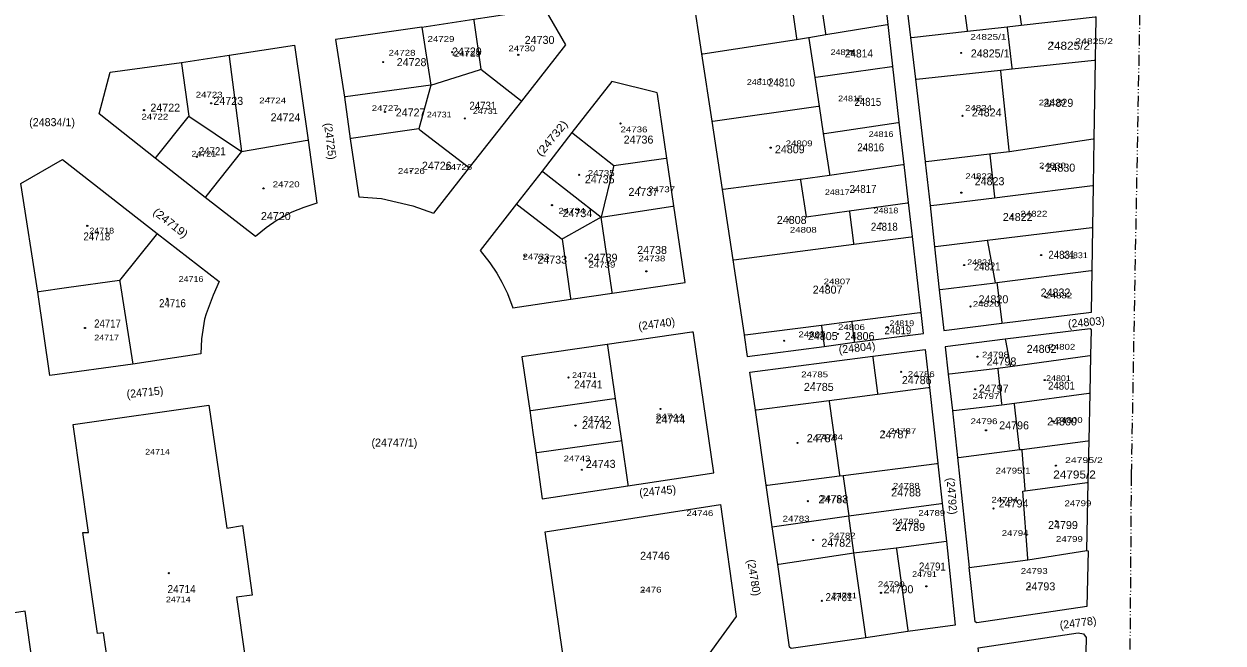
# Model space of a CAD drawing. Extents: x 649608 to 651081, y 237980 to 241202.
# Drawn here: x 650066 to 650605, y 239944 to 240222 of the extents above; entities that cross this region are included whole.
import ezdxf

# ---------------------------------------------------------------- set-up
doc = ezdxf.new("R2010")
doc.units = 0
doc.header["$PDMODE"] = 32
doc.header["$PDSIZE"] = 0.5
doc.linetypes.add('DASH_DOUBLE_DOT', pattern=[9.2, 5, -1.2, 0.3, -1.2, 0.3, -1.2])
for name, color, linetype in [('19', 7, 'Continuous'), ('20', 7, 'Continuous'), ('6', 7, 'Continuous')]:
    doc.layers.add(name, color=color, linetype=linetype)
for name, color, linetype, lineweight in [('3', 7, 'Continuous', 13), ('5', 7, 'Continuous', 13), ('52', 7, 'DASH_DOUBLE_DOT', 13)]:
    doc.layers.add(name, color=color, linetype=linetype, lineweight=lineweight)

msp = doc.modelspace()

# ---------------------------------------------------------------- linework, layer by layer
at = {"layer": '3'}
msp.add_line((650077.677, 240064.155), (650072.262, 240101.751), dxfattribs=at)
for points in [[(650460.37, 240253.655), (650464.813, 240216.218), (650467.034, 240197.497), (650471.435, 240160.411)], [(650459.759, 240178.093), (650456.889, 240203.161), (650456.873, 240203.307), (650454.806, 240222.136), (650451.519, 240252.086)], [(650409.196, 240245.982), (650369.92, 240239.938), (650366.735, 240235.721), (650370.821, 240208.803), (650375.407, 240178.587), (650380.061, 240147.931), (650384.882, 240116.168), (650389.996, 240082.478)], [(650245.029, 240220.902), (650268.31, 240224.434), (650300.106, 240229.259)], [(650300.106, 240229.259), (650309.685, 240212.852), (650289.846, 240187.623), (650266.349, 240157.741), (650250.168, 240137.164)], [(650547.448, 240170.665), (650547.985, 240206.022), (650547.986, 240206.073), (650548.41, 240225.505)], [(650245.029, 240220.902), (650206.077, 240215.362), (650210.154, 240189.431), (650212.761, 240170.721)], [(650158.302, 240208.221), (650187.759, 240212.714), (650193.84, 240170.093)], [(650125.028, 240162.003), (650099.773, 240181.845), (650104.736, 240200.583), (650136.809, 240205.043), (650158.302, 240208.221)], [(650350.909, 240191.305), (650350.427, 240191.426), (650330.438, 240196.449), (650312.536, 240173.446), (650299.057, 240156.125), (650287.566, 240141.36)], [(650355.222, 240162.022), (650351.001, 240190.68), (650350.909, 240191.305)], [(650439.582, 240079.132), (650439.664, 240079.144), (650470.631, 240083.119), (650469.553, 240092.532), (650465.643, 240126.687), (650463.896, 240141.953), (650461.932, 240159.11), (650459.759, 240178.093)], [(650193.84, 240170.093), (650197.735, 240141.656), (650191.852, 240139.818), (650186.467, 240137.627), (650179.884, 240134.109), (650174.936, 240130.596), (650170.183, 240126.658)], [(650212.761, 240170.721), (650216.609, 240144.52), (650226.785, 240143.745), (650240.88, 240140.585), (650250.168, 240137.164)], [(650505.972, 240087.695), (650546.262, 240092.74), (650546.547, 240111.483), (650546.842, 240130.84), (650547.128, 240149.718), (650547.448, 240170.665)], [(650072.262, 240101.751), (650064.598, 240150.503), (650083.395, 240161.316), (650125.86, 240128.041)], [(650170.183, 240126.658), (650147.491, 240144.257), (650125.028, 240162.003)], [(650330.631, 240101.23), (650363.469, 240106.028), (650358.392, 240140.495), (650355.222, 240162.022)], [(650471.435, 240160.411), (650471.464, 240160.171), (650473.598, 240140.628), (650475.618, 240122.131), (650477.734, 240102.751)], [(650287.566, 240141.36), (650271.262, 240120.41), (650275.629, 240114.908), (650278.668, 240110.188), (650280.993, 240106.15), (650283.522, 240101.127), (650285.874, 240094.69), (650311.995, 240098.507), (650330.631, 240101.23)], [(650125.86, 240128.041), (650153.76, 240106.551), (650151.042, 240100.376), (650147.993, 240091.921), (650147.259, 240089.472), (650145.941, 240080.672), (650145.556, 240074.02), (650114.914, 240069.344), (650077.677, 240064.155)], [(650477.734, 240102.751), (650479.737, 240084.41), (650505.972, 240087.695)], [(650545.951, 240073.247), (650546.192, 240084.737), (650545.656, 240085.242), (650507.391, 240080.473)], [(650367.096, 240083.725), (650366.506, 240083.64), (650328.379, 240078.162)], [(650337.721, 240014.61), (650376.316, 240020.498), (650367.171, 240083.212), (650367.096, 240083.725)], [(650389.996, 240082.478), (650390.018, 240082.332), (650391.378, 240072.814), (650426.009, 240077.194)], [(650507.391, 240080.473), (650480.432, 240077.114), (650481.82, 240064.866), (650483.681, 240048.453)], [(650328.379, 240078.162), (650290.024, 240072.651), (650293.54, 240048.426)], [(650426.009, 240077.194), (650426.018, 240077.195), (650439.582, 240079.132)], [(650447.844, 240072.874), (650471.376, 240075.899), (650473.291, 240058.802), (650477.109, 240024.718)], [(650395.057, 240048.659), (650392.582, 240065.771), (650447.844, 240072.874)], [(650544.103, 239985.437), (650544.75, 240016.162), (650545.145, 240034.936), (650545.592, 240056.262), (650545.951, 240073.247)], [(650088.141, 240042.191), (650149.19, 240050.902), (650157.293, 239995.611), (650164.347, 239996.723), (650168.634, 239965.476), (650161.633, 239964.565), (650169.588, 239908.656)], [(650293.54, 240048.426), (650294.974, 240038.545), (650296.256, 240029.457)], [(650402.654, 239996.132), (650399.95, 240014.828), (650395.057, 240048.659)], [(650483.681, 240048.453), (650483.694, 240048.334), (650485.946, 240027.287), (650491.239, 239977.817)], [(650169.588, 239908.656), (650108.765, 239899.717), (650101.708, 239948.509), (650099.051, 239948.199), (650092.508, 239993.558), (650094.984, 239993.566), (650088.141, 240042.191)], [(650296.256, 240029.457), (650299.181, 240008.73), (650337.721, 240014.61)], [(650477.109, 240024.718), (650477.131, 240024.524), (650479.074, 240006.776), (650480.943, 239989.699)], [(650444.775, 239946.285), (650411.125, 239941.373), (650410.377, 239941.975), (650405.07, 239979.206), (650402.654, 239996.132)], [(650480.943, 239989.699), (650484.938, 239951.984), (650463.613, 239949.096), (650444.775, 239946.285)], [(650544.103, 239985.437), (650544.781, 239985.332), (650544.163, 239960.292), (650494.592, 239952.965), (650493.943, 239953.442), (650491.239, 239977.817)], [(650071.051, 239926.074), (650066.514, 239958.205), (650038.223, 239953.835), (650015.835, 239950.432), (649993.523, 239946.827), (649971.163, 239943.727)]]:
    msp.add_lwpolyline(points, dxfattribs=at)
for points in [[(650379.366, 240006.183), (650386.357, 239955.842), (650374.029, 239938.824), (650309.84, 239928.724), (650300.505, 239993.965)], [(650541.896, 239857.35), (650505.729, 239851.839), (650495.324, 239941.714), (650540.294, 239948.511), (650542.677, 239948.068), (650543.767, 239946.296)]]:
    msp.add_lwpolyline(points, close=True, dxfattribs=at)
at = {"layer": '5'}
for p, q in [((650245.029, 240220.902), (650249.078, 240194.772)), ((650249.078, 240194.772), (650243.626, 240175.122)), ((650515.319, 240012.253), (650516.434, 240012.401)), ((650402.654, 239996.132), (650437.147, 240001.148))]:
    msp.add_line(p, q, dxfattribs=at)
for points in [[(650508.951, 240260.965), (650509.023, 240260.465), (650514.54, 240222.272), (650514.612, 240221.772)], [(650485.214, 240257.393), (650485.282, 240256.893), (650490.357, 240219.574), (650490.425, 240219.074)], [(650422.153, 240247.787), (650422.228, 240247.287), (650426.646, 240218.032), (650426.721, 240217.532)], [(650409.196, 240245.982), (650409.268, 240245.482), (650413.524, 240215.891), (650413.596, 240215.391)], [(650514.612, 240221.772), (650547.91, 240225.45), (650548.41, 240225.505)], [(650268.31, 240224.434), (650268.38, 240223.934), (650271.472, 240201.911)], [(650426.721, 240217.532), (650454.306, 240222.054), (650454.806, 240222.136)], [(650464.813, 240216.218), (650465.313, 240216.274), (650490.425, 240219.074), (650508.256, 240221.063)], [(650508.256, 240221.063), (650514.585, 240221.769), (650514.612, 240221.772)], [(650508.256, 240221.063), (650508.316, 240220.563), (650510.473, 240202.605), (650510.533, 240202.105)], [(650370.821, 240208.803), (650371.321, 240208.88), (650413.525, 240215.38), (650413.596, 240215.391)], [(650413.596, 240215.391), (650418.994, 240216.265), (650419.023, 240216.27), (650426.721, 240217.532)], [(650419.023, 240216.27), (650419.099, 240215.77), (650421.759, 240198.257), (650423.715, 240185.381), (650425.591, 240173.032)], [(650136.809, 240205.043), (650136.878, 240204.543), (650140.128, 240180.885), (650163.898, 240165.01)], [(650158.302, 240208.221), (650158.367, 240207.721), (650163.898, 240165.01)], [(650510.533, 240202.105), (650547.486, 240206.02), (650547.986, 240206.073)], [(650249.078, 240194.772), (650270.972, 240201.752), (650271.472, 240201.911)], [(650271.472, 240201.911), (650289.346, 240188.012), (650289.846, 240187.623)], [(650421.759, 240198.257), (650422.259, 240198.329), (650456.373, 240203.235), (650456.873, 240203.307)], [(650467.034, 240197.497), (650467.534, 240197.55), (650505.242, 240201.545), (650510.533, 240202.105)], [(650505.242, 240201.545), (650505.296, 240201.045), (650509.108, 240165.48), (650509.162, 240164.98)], [(650249.078, 240194.772), (650210.654, 240189.5), (650210.154, 240189.431)], [(650375.407, 240178.587), (650375.907, 240178.657), (650423.215, 240185.311), (650423.715, 240185.381)], [(650140.128, 240180.885), (650139.728, 240180.385), (650125.428, 240162.503), (650125.028, 240162.003)], [(650425.591, 240173.032), (650426.091, 240173.106), (650459.259, 240178.019), (650459.759, 240178.093)], [(650243.626, 240175.122), (650213.261, 240170.792), (650212.761, 240170.721)], [(650243.626, 240175.122), (650244.126, 240174.74), (650265.849, 240158.123), (650266.349, 240157.741)], [(650312.536, 240173.446), (650313.037, 240173.052), (650331.361, 240158.63)], [(650425.591, 240173.032), (650428.351, 240154.86), (650428.427, 240154.36)], [(650163.898, 240165.01), (650193.34, 240170.008), (650193.84, 240170.093)], [(650509.162, 240164.98), (650509.317, 240164.999), (650546.947, 240170.591), (650547.448, 240170.665)], [(650163.898, 240165.01), (650147.886, 240144.757), (650147.491, 240144.257)], [(650331.361, 240158.63), (650354.722, 240161.951), (650355.222, 240162.022)], [(650471.435, 240160.411), (650471.936, 240160.472), (650500.379, 240163.916), (650509.162, 240164.98)], [(650500.379, 240163.916), (650500.436, 240163.416), (650502.571, 240144.62), (650502.628, 240144.12)], [(650299.057, 240156.125), (650299.557, 240155.736), (650325.588, 240135.477)], [(650331.361, 240158.63), (650331.236, 240158.13), (650325.588, 240135.477)], [(650428.427, 240154.36), (650461.432, 240159.039), (650461.932, 240159.11)], [(650380.061, 240147.931), (650380.561, 240147.996), (650415.222, 240152.488), (650415.26, 240152.493), (650428.427, 240154.36)], [(650415.26, 240152.493), (650415.337, 240151.993), (650417.881, 240135.578), (650437.28, 240138.266)], [(650502.628, 240144.12), (650508.4, 240144.814), (650546.629, 240149.655), (650547.128, 240149.718)], [(650287.566, 240141.36), (650288.066, 240140.972), (650308.044, 240125.473)], [(650325.588, 240135.477), (650357.892, 240140.419), (650358.392, 240140.495)], [(650437.28, 240138.266), (650463.396, 240141.884), (650463.896, 240141.953)], [(650473.598, 240140.628), (650474.098, 240140.688), (650502.628, 240144.12)], [(650325.588, 240135.477), (650308.544, 240125.758), (650308.044, 240125.473)], [(650330.631, 240101.23), (650330.557, 240101.73), (650325.588, 240135.477)], [(650437.28, 240138.266), (650437.346, 240137.766), (650439.187, 240123.75), (650439.253, 240123.25)], [(650499.333, 240125.031), (650546.341, 240130.779), (650546.842, 240130.84)], [(650125.86, 240128.041), (650125.46, 240127.541), (650109.022, 240106.971)], [(650308.044, 240125.473), (650311.922, 240099.007), (650311.995, 240098.507)], [(650384.882, 240116.168), (650385.382, 240116.233), (650439.253, 240123.25)], [(650439.253, 240123.25), (650465.143, 240126.622), (650465.643, 240126.687)], [(650475.618, 240122.131), (650476.118, 240122.192), (650499.333, 240125.031)], [(650499.333, 240125.031), (650499.426, 240124.531), (650502.886, 240105.943)], [(650109.022, 240106.971), (650085.163, 240103.599), (650072.762, 240101.823), (650072.262, 240101.751)], [(650109.022, 240106.971), (650109.1, 240106.471), (650114.914, 240069.344)], [(650503.673, 240106.043), (650546.047, 240111.42), (650546.547, 240111.483)], [(650477.734, 240102.751), (650478.234, 240102.814), (650502.886, 240105.943), (650503.673, 240106.043)], [(650503.673, 240106.043), (650505.909, 240088.195), (650505.972, 240087.695)], [(650438.352, 240088.589), (650469.053, 240092.469), (650469.553, 240092.532)], [(650389.996, 240082.478), (650390.496, 240082.541), (650424.708, 240086.865), (650438.352, 240088.589)], [(650424.708, 240086.865), (650424.775, 240086.365), (650425.942, 240077.694), (650426.009, 240077.194)], [(650438.352, 240088.589), (650438.417, 240088.089), (650439.517, 240079.632), (650439.582, 240079.132)], [(650507.391, 240080.473), (650507.487, 240079.973), (650509.626, 240068.796), (650509.722, 240068.296)], [(650328.379, 240078.162), (650328.452, 240077.662), (650331.951, 240053.863), (650334.735, 240034.921)], [(650447.844, 240072.874), (650447.908, 240072.374), (650449.973, 240056.287), (650450.037, 240055.787)], [(650509.722, 240068.296), (650545.45, 240073.179), (650545.951, 240073.247)], [(650481.82, 240064.866), (650482.32, 240064.925), (650504.076, 240067.513), (650509.722, 240068.296)], [(650504.076, 240067.513), (650504.131, 240067.013), (650505.817, 240051.54), (650505.872, 240051.04)], [(650450.037, 240055.787), (650472.791, 240058.737), (650473.291, 240058.802)], [(650293.54, 240048.426), (650294.04, 240048.497), (650331.451, 240053.792), (650331.951, 240053.863)], [(650395.057, 240048.659), (650395.557, 240048.724), (650428.194, 240052.955), (650450.037, 240055.787)], [(650428.194, 240052.955), (650428.263, 240052.455), (650432.806, 240019.548), (650432.875, 240019.048)], [(650511.602, 240051.793), (650545.093, 240056.196), (650545.592, 240056.262)], [(650483.681, 240048.453), (650484.18, 240048.511), (650505.872, 240051.04), (650511.602, 240051.793)], [(650513.938, 240030.85), (650513.882, 240031.35), (650511.658, 240051.293), (650511.602, 240051.793)], [(650296.256, 240029.457), (650296.756, 240029.528), (650334.235, 240034.85), (650334.735, 240034.921)], [(650334.735, 240034.921), (650337.648, 240015.11), (650337.721, 240014.61)], [(650514.967, 240030.918), (650544.644, 240034.869), (650545.145, 240034.936)], [(650485.946, 240027.287), (650486.446, 240027.351), (650513.938, 240030.85)], [(650513.938, 240030.85), (650514.959, 240030.917), (650514.967, 240030.918)], [(650516.434, 240012.401), (650516.394, 240012.901), (650515.007, 240030.418), (650514.967, 240030.918)], [(650434.481, 240019.254), (650476.609, 240024.654), (650477.109, 240024.718)], [(650399.95, 240014.828), (650400.45, 240014.892), (650432.875, 240019.048), (650434.481, 240019.254)], [(650434.481, 240019.254), (650434.555, 240018.754), (650437.147, 240001.148)], [(650516.434, 240012.401), (650544.249, 240016.096), (650544.75, 240016.162)], [(650517.669, 239981.354), (650517.631, 239981.854), (650515.319, 240012.253)], [(650437.147, 240001.148), (650478.574, 240006.709), (650479.074, 240006.776)], [(650444.775, 239946.285), (650444.704, 239946.785), (650439.351, 239984.386), (650437.147, 240001.148)], [(650405.07, 239979.206), (650405.57, 239979.282), (650439.351, 239984.386), (650458.41, 239986.649), (650480.943, 239989.699)], [(650458.41, 239986.649), (650458.479, 239986.149), (650463.544, 239949.596), (650463.613, 239949.096)], [(650491.239, 239977.817), (650517.669, 239981.354), (650544.103, 239985.437)]]:
    msp.add_lwpolyline(points, dxfattribs=at)
at = {"layer": '52'}
msp.add_lwpolyline([(650605.404, 240765.589), (650575.102, 240622.376), (650564.111, 240019.547), (650563.292, 239912.239), (650561.967, 239831.306), (650558.948, 239635.138), (650557.76, 239590.469), (650555.824, 239499.761), (650555.114, 239481.758), (650553.994, 239393.396), (650554.019, 239393.395), (650553.222, 239318.763), (650553.006, 239301.006), (650586.911, 239277.281)], dxfattribs=at)
at = {"layer": '6'}
for p in [(650258.586, 240209.603), (650438.031, 240210.196), (650487.654, 240209.28), (650528.641, 240213.805), (650227.574, 240205.166), (650288.386, 240208.441), (650397.216, 240197.428), (650175.986, 240188.862), (650440.948, 240188.169), (650119.992, 240183.523), (650150.221, 240186.615), (650228.413, 240182.746), (650527.317, 240185.526), (650264.323, 240179.826), (650334.329, 240177.539), (650488.221, 240180.978), (650401.889, 240166.656), (650443.871, 240166.226), (650143.726, 240162.571), (650239.997, 240156.143), (650524.183, 240157.392), (650315.758, 240154.461), (650173.781, 240148.375), (650343.037, 240148.749), (650439.668, 240147.344), (650487.663, 240146.45), (650303.519, 240140.799), (650409.961, 240134.33), (650510.515, 240135.924), (650094.492, 240131.533), (650451.495, 240132.601), (650291.145, 240118.025), (650523.611, 240118.391), (650318.798, 240116.992), (650488.962, 240113.891), (650345.958, 240111.046), (650427.407, 240104.582), (650130.376, 240098.692), (650525.424, 240099.589), (650491.792, 240095.226), (650093.484, 240085.563), (650454.515, 240085.832), (650408.014, 240079.839), (650432.168, 240082.891), (650527.063, 240076.769), (650494.91, 240072.669), (650310.973, 240063.294), (650460.624, 240065.843), (650421.352, 240060.766), (650493.858, 240057.983), (650525.189, 240062.143), (650352.388, 240049.167), (650528.923, 240043.556), (650314.133, 240041.66), (650452.824, 240038.925), (650498.802, 240039.54), (650414.009, 240033.891), (650316.997, 240021.825), (650530.225, 240023.668), (650456.906, 240012.933), (650418.583, 240007.693), (650502.159, 240004.367), (650530.364, 239998.758), (650459.089, 239995.581), (650421.047, 239990.177), (650131.213, 239975.309), (650344.522, 239967.453), (650451.554, 239966.467), (650471.947, 239969.397), (650518.289, 239969.201), (650424.905, 239962.879)]:
    msp.add_point(p, dxfattribs=at)

# ---------------------------------------------------------------- texts
at = {"layer": '19'}
for s, p in [('24730', (650291.263, 240213.344)), ('24729', (650258.545, 240208.12)), ('24825/1', (650491.945, 240207.25)), ('24728', (650233.677, 240203.331)), ('24723', (650151.225, 240185.919)), ('24829', (650524.665, 240185.047)), ('24722', (650122.868, 240182.871)), ('24727', (650233.242, 240180.694)), ('24824', (650492.381, 240180.694)), ('(24834/1)', (650068.337, 240176.34)), ('24724', (650176.963, 240178.518)), ('24736', (650335.764, 240168.504)), ('24809', (650403.819, 240164.151)), ('24726', (650245.021, 240156.75)), ('24830', (650525.538, 240155.88)), ('24735', (650318.313, 240150.655)), ('24823', (650493.689, 240149.785)), ('24737', (650337.945, 240144.996)), ('24734', (650308.278, 240135.419)), ('24720', (650172.601, 240134.113)), ('24808', (650404.691, 240132.371)), ('24822', (650506.341, 240133.677)), ('24733', (650296.936, 240114.522)), ('24739', (650319.622, 240115.393)), ('24738', (650341.871, 240118.876)), ('24807', (650420.833, 240101.027)), ('24832', (650523.356, 240099.721)), ('24820', (650495.435, 240096.673)), ('24805', (650418.652, 240080.13)), ('24806', (650435.23, 240080.13)), ('24742', (650317.003, 240040.079)), ('24744', (650350.159, 240042.691)), ('(24747/1)', (650222.336, 240032.243)), ('24743', (650318.748, 240022.666)), ('24746', (650343.18, 239981.308))]:
    msp.add_text(s, height=3.6, dxfattribs=at).set_placement(p)
for s, width, p in [('24814', 0.95, (650435.23, 240207.25)), ('24825/2', 1.1, (650526.409, 240210.732)), ('24810', 0.9, (650400.765, 240194.189)), ('24815', 0.9, (650439.592, 240185.483)), ('24731', 0.9, (650266.398, 240183.741)), ('24721', 0.9, (650144.681, 240163.281)), ('24816', 0.9, (650440.902, 240165.022)), ('24817', 0.9, (650437.412, 240146.302)), ('24718', 0.9, (650092.766, 240124.969)), ('24818', 0.9, (650447.009, 240129.324)), ('24831', 0.9, (650526.846, 240116.699)), ('24821', 0.9, (650493.253, 240111.475)), ('24716', 0.9, (650126.796, 240094.932)), ('24717', 0.9, (650097.567, 240085.79)), ('24819', 0.9, (650453.117, 240082.742)), ('24741', 0.95, (650313.513, 240058.364)), ('24795/2', 1.1, (650529.026, 240017.877)), ('24714', 0.95, (650130.556, 239966.341))]:
    msp.add_text(s, height=3.6, dxfattribs=dict(at, width=width)).set_placement(p)
for s, rotation, p in [('(24725)', 277.149, (650200.946, 240177.578)), ('(24803)', 5.28, (650535.827, 240085.657)), ('(24740)', 7.526, (650342.635, 240084.562)), ('(24804)', 6.245, (650432.699, 240074.011)), ('24802', 359.954, (650517.108, 240074.389)), ('24798', 359.954, (650499.05, 240068.728)), ('24786', 359.954, (650460.927, 240060.327)), ('(24715)', 6.099, (650112.358, 240054.009)), ('24785', 359.954, (650416.864, 240057.279)), ('24797', 359.954, (650495.559, 240056.539)), ('24796', 359.954, (650504.721, 240039.996)), ('24800', 359.954, (650526.27, 240041.738)), ('24784', 359.954, (650418.172, 240034.206)), ('24787', 359.954, (650450.893, 240035.947)), ('(24792)', 274.247, (650481.045, 240018.106)), ('(24745)', 5.509, (650342.968, 240009.716)), ('24783', 359.954, (650423.408, 240006.779)), ('24788', 359.954, (650456.127, 240009.827)), ('24794', 359.954, (650504.474, 240004.862)), ('24799', 359.954, (650526.706, 239995.157)), ('24789', 359.954, (650457.972, 239994.266)), ('24782', 359.954, (650424.717, 239987.189)), ('(24780)', 279.312, (650391.295, 239981.202)), ('24790', 359.954, (650452.716, 239966.273)), ('24793', 359.954, (650516.555, 239967.568)), ('(24778)', 7.402, (650532.186, 239950.139))]:
    msp.add_text(s, height=3.6, rotation=rotation, dxfattribs=at).set_placement(p)
for s, rotation, width, p in [('(24732)', 50.821, 1.15, (650298.841, 240162.371)), ('(24719)', 321.889, 1.1, (650123.677, 240137.063)), ('24801', 359.954, 0.9, (650526.706, 240057.846)), ('24791', 359.954, 0.9, (650468.629, 239976.501)), ('24781', 359.954, 0.9, (650426.599, 239962.727))]:
    msp.add_text(s, height=3.6, rotation=rotation, dxfattribs=dict(at, width=width)).set_placement(p)
at = {"layer": '20'}
for s, width, p in [('24729', 1.25, (650247.567, 240214.264)), ('24825/1', 1.3, (650491.673, 240215.19)), ('24825/2', 1.35, (650538.936, 240213.247)), ('24728', 1.25, (650230.038, 240208.062)), ('24729', 1.25, (650259.409, 240207.597)), ('24730', 1.25, (650283.914, 240210.004)), ('24814', 1.15, (650428.88, 240208.335)), ('24810', 1.15, (650391.2, 240194.887)), ('24723', 1.25, (650143.276, 240189.227)), ('24724', 1.25, (650171.832, 240186.603)), ('24815', 1.15, (650432.269, 240187.483)), ('24829', 1.25, (650522.493, 240185.663)), ('24727', 1.25, (650222.451, 240183.131)), ('24731', 1.15, (650247.241, 240180.268)), ('24731', 1.15, (650267.979, 240181.869)), ('24824', 1.25, (650489.37, 240183.262)), ('24722', 1.25, (650118.847, 240179.326)), ('24736', 1.25, (650334.388, 240173.583)), ('24816', 1.15, (650446.002, 240171.473)), ('24809', 1.25, (650408.677, 240167.308)), ('24721', 1.15, (650141.343, 240162.626)), ('24726', 1.25, (650234.239, 240154.86)), ('24726', 1.25, (650255.545, 240156.69)), ('24735', 1.25, (650319.637, 240153.963)), ('24830', 1.25, (650522.638, 240157.335)), ('24720', 1.25, (650177.91, 240148.908)), ('24823', 1.25, (650489.472, 240152.522)), ('24737', 1.25, (650346.802, 240146.652)), ('24817', 1.15, (650426.313, 240145.375)), ('24734', 1.25, (650306.45, 240137.003)), ('24818', 1.15, (650448.202, 240137.127)), ('24822', 1.25, (650514.283, 240135.679)), ('24718', 1.15, (650095.431, 240128.062)), ('24808', 1.25, (650410.534, 240128.428)), ('24733', 1.25, (650290.297, 240116.365)), ('24738', 1.25, (650342.439, 240115.532)), ('24831', 1.15, (650533.439, 240116.984)), ('24739', 1.25, (650319.958, 240112.755)), ('24821', 1.15, (650490.335, 240113.838)), ('24716', 1.15, (650135.615, 240106.298)), ('24807', 1.25, (650425.752, 240105.199)), ('24832', 1.25, (650525.463, 240098.889)), ('24820', 1.25, (650492.847, 240095.094)), ('24806', 1.25, (650432.211, 240084.654)), ('24819', 1.15, (650455.325, 240086.412)), ('24717', 1.15, (650097.625, 240079.966)), ('24805', 1.25, (650414.407, 240081.414)), ('24798', 1.25, (650496.998, 240072.312)), ('24802', 1.25, (650526.865, 240075.822)), ('24741', 1.15, (650312.574, 240063.055)), ('24785', 1.25, (650415.658, 240063.402)), ('24786', 1.25, (650463.608, 240063.536)), ('24801', 1.15, (650525.816, 240061.693)), ('24797', 1.25, (650492.695, 240053.617)), ('24742', 1.25, (650317.376, 240043.353)), ('24744', 1.3, (650350.163, 240044.454)), ('24796', 1.25, (650491.845, 240042.327)), ('24800', 1.25, (650530.157, 240042.882)), ('24784', 1.25, (650422.318, 240035.216)), ('24787', 1.25, (650455.299, 240037.9)), ('24714', 1.15, (650120.539, 240028.603)), ('24743', 1.25, (650308.752, 240025.574)), ('24795/2', 1.35, (650534.352, 240024.835)), ('24795/1', 1.25, (650503.093, 240020.115)), ('24788', 1.25, (650456.885, 240013.304)), ('24783', 1.25, (650424.389, 240007.638)), ('24794', 1.25, (650501.214, 240007.011)), ('24799', 1.25, (650534.1, 240005.433)), ('24746', 1.25, (650364.016, 240000.994)), ('24783', 1.25, (650407.313, 239998.527)), ('24789', 1.25, (650456.596, 239997.255)), ('24789', 1.25, (650468.357, 240001.088)), ('24782', 1.25, (650428.064, 239990.896)), ('24794', 1.25, (650505.834, 239992.041)), ('24799', 1.25, (650530.257, 239989.37)), ('24793', 1.25, (650514.428, 239974.999)), ('24791', 1.15, (650465.545, 239973.6)), ('2476', 1.25, (650343.127, 239966.581)), ('24781', 1.15, (650429.533, 239963.935)), ('24790', 1.25, (650450.119, 239969.022)), ('24714', 1.15, (650129.86, 239962.165))]:
    msp.add_text(s, height=2.6, dxfattribs=dict(at, width=width)).set_placement(p)

doc.saveas('drawing.dxf')
